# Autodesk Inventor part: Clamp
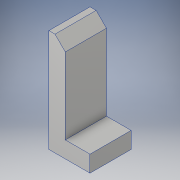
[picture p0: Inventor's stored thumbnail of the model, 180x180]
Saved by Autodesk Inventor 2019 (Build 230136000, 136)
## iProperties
Created: 2018-07
Part Number: Clamp
Material: Aluminum 6061
Description: 123456
Document SubType Name: Modeling
Designer: Power User
Mass: 26.109 g
Surface Area: 37.0842 cm^2
Volume: 9.67 cm^3
Density: 2.7 g/cm^3
Appearance: Aluminum - Flat
Title: GEAR
Author: Power User
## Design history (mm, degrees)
sketch "Sketch6"
  geometry: L1 (0, 0)-(0, 50); L2 (0, 50)-(8, 50); L3 (8, 50)-(8, 8); L4 (8, 8)-(20, 8); L5 (20, 8)-(20, 0); L6 (20, 0)-(0, 0)
  constraints: 12 end point, 5 perpendicular, 1 vertical
  dimensions: "d44" = 20 distance of L5.end L1.start; "d45" = 12 distance of L3.end L4.end; "d46" = 50 distance of L1.start L1.end; "d47" = 8 distance of L4.end L5.end
extrude "Extrusion5" new body sketch "Sketch6" stored distance "d48" = 20; taper "d49" = 0 deg
chamfer "Chamfer2" distance "d50" = 5; stored, may be unused: second distance "d51" = 5, angle "d52" = 45 deg
body "Solid2"
